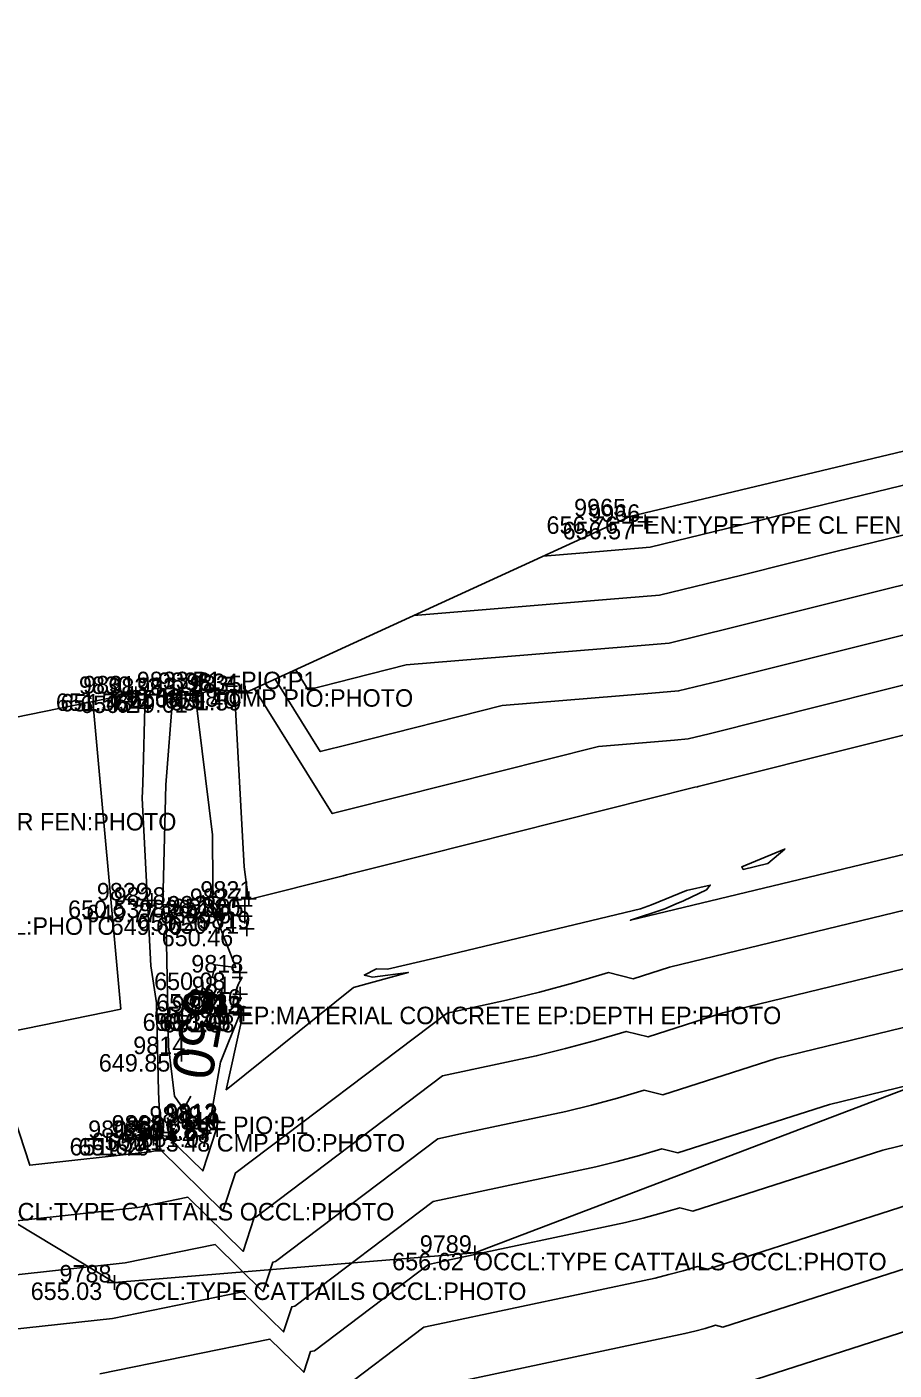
# Model space of a CAD drawing. Extents: x 2129350 to 2137777, y 657588 to 659885.
# Drawn here: x 2133958.2 to 2134017.7, y 659044.8 to 659137 of the extents above; entities that cross this region are included whole.
import ezdxf

# ---------------------------------------------------------------- set-up
doc = ezdxf.new("R2010")
doc.units = 0
for name, color, linetype in [('DT_X_Contour_Major', 7, 'Continuous'), ('DT_X_Contour_Minor', 7, 'Continuous'), ('DT_X_TIN_Hull', 7, 'Continuous'), ('SV_X_Occupation_Line', 7, 'Continuous'), ('SV_X_Shot_Marker', 7, 'Continuous'), ('SV_X_Text_Comment', 7, 'Continuous'), ('SV_X_Text_Description', 7, 'Continuous'), ('SV_X_Text_Elevation', 7, 'Continuous'), ('SV_X_Text_Name', 7, 'Continuous')]:
    doc.layers.add(name, color=color, linetype=linetype)

msp = doc.modelspace()

# ---------------------------------------------------------------- linework, layer by layer
at = {"layer": 'DT_X_Contour_Major'}
for points in [[(2133984.763, 659096.562), (2133998.002, 659097.665), (2134001.64, 659097.968), (2134007.291, 659099.346), (2134013.833, 659100.986), (2134031.695, 659105.339), (2134035.772, 659106.371), (2134054.144, 659110.846), (2134059.912, 659112.305), (2134062.733, 659113.033), (2134082.191, 659118.049), (2134082.236, 659118.06)], [(2133970.96, 659071.806), (2133971.072, 659072.3), (2133971.145, 659072.61), (2133972.548, 659072.42), (2133971.228, 659075.803), (2133971.01, 659076.039), (2133970.955, 659081.1), (2133970.959, 659081.519), (2133969.763, 659091.144)], [(2133968.348, 659091.104), (2133968.238, 659091.09), (2133967.752, 659084.944), (2133967.54, 659076.833), (2133967.77, 659075.29), (2133967.948, 659067.002), (2133968.355, 659063.607), (2133968.956, 659062.7), (2133969.468, 659063.591)], [(2133949.597, 659046.76), (2133964.098, 659048.355), (2133973.018, 659050.173), (2133975.83, 659047.42), (2133976.393, 659049.146), (2133976.617, 659049.192), (2133986.103, 659056.365), (2133987.605, 659056.69), (2133997.253, 659058.741), (2133998.731, 659059.107), (2134000.25, 659059.52), (2134001.796, 659059.974), (2134002.899, 659059.699), (2134013.292, 659063.037), (2134025.401, 659065.979), (2134026.335, 659066.172), (2134030.508, 659067.186), (2134032.419, 659068.346), (2134033.637, 659067.879), (2134042.451, 659069.822)]]:
    msp.add_lwpolyline(points, dxfattribs=at)
at = {"layer": 'DT_X_Contour_Minor'}
for points in [[(2133976.674, 659092.847), (2133977.522, 659091.483), (2133980.569, 659092.251), (2133984.24, 659093.177), (2133999.557, 659094.453), (2134002.293, 659094.681), (2134006.542, 659095.717), (2134017.451, 659098.452), (2134030.921, 659101.735), (2134037.914, 659103.505), (2134051.837, 659106.896), (2134062.046, 659109.479), (2134064.2, 659110.034), (2134079.051, 659113.863), (2134086.408, 659115.608), (2134096.359, 659117.968), (2134110.672, 659121.688), (2134113.284, 659122.316), (2134123.738, 659124.847), (2134133.178, 659127.116), (2134143.637, 659129.649), (2134152.762, 659131.842), (2134168.026, 659135.54)], [(2134167.919, 659131.932), (2134158.207, 659129.579), (2134143.576, 659126.064), (2134136.854, 659124.435), (2134122.145, 659120.901), (2134115.361, 659119.258), (2134111.231, 659118.265), (2134101.918, 659115.845), (2134086.965, 659112.298), (2134075.91, 659109.676), (2134065.666, 659107.035), (2134064.18, 659106.652), (2134049.53, 659102.946), (2134040.056, 659100.638), (2134030.148, 659098.13), (2134021.07, 659095.918), (2134005.794, 659092.088), (2134002.946, 659091.394), (2134001.112, 659091.241), (2133990.847, 659090.386), (2133980.378, 659087.745), (2133978.347, 659087.233), (2133975.261, 659092.198)], [(2133993.65, 659100.644), (2133996.447, 659100.877), (2134000.987, 659101.255), (2134008.04, 659102.975), (2134010.215, 659103.52), (2134032.469, 659108.943), (2134033.63, 659109.237), (2134056.451, 659114.796), (2134057.778, 659115.132), (2134061.267, 659116.032), (2134084.359, 659121.985), (2134084.561, 659122.058), (2134088.214, 659123.011), (2134109.184, 659128.595), (2134118.743, 659130.987)], [(2134163.653, 659127.317), (2134143.515, 659122.478), (2134140.529, 659121.755), (2134120.552, 659116.954), (2134117.438, 659116.2), (2134111.791, 659114.843), (2134107.476, 659113.722), (2134087.522, 659108.989), (2134072.77, 659105.489), (2134067.132, 659104.036), (2134066.314, 659103.825), (2134047.223, 659098.996), (2134042.198, 659097.772), (2134029.374, 659094.526), (2134024.688, 659093.384), (2134005.045, 659088.459), (2134003.599, 659088.107), (2134002.668, 659088.029), (2133997.455, 659087.595), (2133980.186, 659083.24), (2133979.173, 659082.984), (2133973.849, 659091.549)], [(2134095.816, 659107.514), (2134088.079, 659105.679), (2134069.63, 659101.303), (2134068.598, 659101.037), (2134068.448, 659100.998), (2134044.916, 659095.046), (2134044.34, 659094.906), (2134028.6, 659090.922), (2134028.306, 659090.85), (2134004.296, 659084.83), (2134004.251, 659084.82), (2134004.223, 659084.817), (2134004.063, 659084.804), (2133982.451, 659079.354), (2133980.16, 659078.782), (2133979.923, 659078.72), (2133973.446, 659077.098), (2133973.417, 659077.074), (2133973.133, 659079.326), (2133972.456, 659091.406)], [(2133966.328, 659091.154), (2133966.179, 659085.021), (2133966.132, 659084.042), (2133966.732, 659072.529), (2133967.109, 659070), (2133967.24, 659063.89), (2133967.398, 659060.899), (2133967.856, 659060.846), (2133970.284, 659058.468), (2133971.205, 659061.291), (2133971.257, 659061.318), (2133970.798, 659061.748), (2133970.765, 659061.8), (2133971.506, 659065.941), (2133972.802, 659069.177), (2133972.807, 659069.197), (2133972.801, 659069.373), (2133972.939, 659069.216), (2133972.939, 659069.194), (2133972.952, 659068.84), (2133972.952, 659068.822), (2133972.921, 659068.684), (2133971.901, 659064.036), (2133980.635, 659071.043), (2133984.389, 659072.088), (2133981.931, 659071.766), (2133981.659, 659071.831), (2133981.367, 659071.901), (2133982.216, 659072.326), (2133982.975, 659072.314), (2133986.215, 659073.069), (2134000.328, 659076.44), (2134001.091, 659076.732), (2134003.49, 659077.7), (2134005.113, 659078.081), (2134004.854, 659077.758), (2134003.279, 659077.002), (2134002.787, 659076.786), (2134001.995, 659076.438), (2133999.642, 659075.668), (2134018.561, 659080.227)], [(2133962.734, 659090.671), (2133964.656, 659069.566), (2133945.043, 659065.553)], [(2133985.855, 659043.583), (2134003.377, 659047.309), (2134004.058, 659047.477), (2134004.757, 659047.668), (2134005.469, 659047.877), (2134005.976, 659047.75), (2134024.269, 659053.625), (2134028.407, 659054.63), (2134030.054, 659054.97), (2134031.451, 659055.309), (2134034.821, 659057.356), (2134036.97, 659056.532), (2134041.073, 659057.437), (2134056.258, 659058.478), (2134069.282, 659066.027), (2134077.71, 659067.617), (2134077.927, 659067.658), (2134087.349, 659069.428), (2134121.013, 659079.703), (2134124.053, 659080.211), (2134127.308, 659081.14), (2134164.102, 659088.042)], [(2133963.234, 659044.551), (2133974.897, 659046.928), (2133977.216, 659044.658), (2133977.681, 659046.081), (2133977.961, 659046.138), (2133985.783, 659052.053), (2133987.022, 659052.321), (2133999.295, 659054.931), (2134000.507, 659055.23), (2134001.752, 659055.57), (2134003.02, 659055.942), (2134003.924, 659055.716), (2134016.951, 659059.9), (2134026.403, 659062.196), (2134027.575, 659062.438), (2134030.823, 659063.227), (2134033.22, 659064.682), (2134034.748, 659064.097), (2134044.461, 659066.238), (2134055.463, 659066.993), (2134072.632, 659076.944), (2134074.956, 659077.482), (2134078.271, 659078.486), (2134116.21, 659087.131)], [(2133979.305, 659043.085), (2133985.463, 659047.741), (2133986.439, 659047.952), (2134001.336, 659051.12), (2134002.282, 659051.354), (2134003.255, 659051.619), (2134004.244, 659051.909), (2134004.95, 659051.733), (2134020.61, 659056.762), (2134027.405, 659058.413), (2134028.814, 659058.704), (2134031.137, 659059.268), (2134034.021, 659061.019), (2134035.859, 659060.314), (2134042.767, 659061.837), (2134055.861, 659062.736), (2134074.558, 659073.572), (2134075.929, 659073.831), (2134075.965, 659073.838), (2134077.498, 659074.126), (2134086.096, 659076.75), (2134120.442, 659084.577)], [(2134007.002, 659043.767), (2134027.928, 659050.488), (2134029.41, 659050.848), (2134031.294, 659051.236), (2134031.765, 659051.351), (2134035.622, 659053.692), (2134038.081, 659052.75), (2134039.378, 659053.036), (2134056.656, 659054.221), (2134064.007, 659058.482), (2134079.49, 659061.402), (2134079.89, 659061.478), (2134097.201, 659064.73), (2134113.485, 659069.7), (2134126.289, 659071.838), (2134139.998, 659075.753), (2134158.234, 659079.174), (2134175.353, 659083.764)], [(2134010.206, 659080.536), (2134010.237, 659080.549), (2134010.225, 659080.538), (2134009.064, 659079.551), (2134007.382, 659079.153), (2134007.272, 659079.32), (2134010.206, 659080.536)], [(2133957.38, 659062.078), (2133958.413, 659058.858), (2133966.69, 659059.769), (2133967.378, 659059.909), (2133971.67, 659055.706), (2133972.53, 659058.341), (2133972.585, 659058.352), (2133987.063, 659069.3), (2133989.356, 659069.797), (2133991.13, 659070.174), (2133993.405, 659070.736), (2133995.743, 659071.373), (2133998.123, 659072.072), (2133999.821, 659071.649), (2134002.314, 659072.449), (2134022.394, 659077.328)], [(2133943.581, 659053.517), (2133965.826, 659055.964), (2133969.258, 659056.664), (2133973.057, 659052.944), (2133973.818, 659055.276), (2133973.929, 659055.299), (2133986.743, 659064.988), (2133988.772, 659065.428), (2133993.171, 659066.363), (2133995.181, 659066.859), (2133997.246, 659067.422), (2133999.347, 659068.039), (2134000.847, 659067.665), (2134005.973, 659069.312), (2134023.397, 659073.545)], [(2133945.621, 659050.032), (2133964.962, 659052.16), (2133971.138, 659053.419), (2133974.443, 659050.182), (2133975.105, 659052.211), (2133975.273, 659052.245), (2133986.423, 659060.677), (2133988.189, 659061.059), (2133995.212, 659062.552), (2133996.956, 659062.983), (2133998.748, 659063.471), (2134000.571, 659064.007), (2134001.873, 659063.682), (2134009.632, 659066.175), (2134024.399, 659069.762)]]:
    msp.add_lwpolyline(points, dxfattribs=at)
at = {"layer": 'DT_X_TIN_Hull'}
msp.add_lwpolyline([(2134356.026, 659185.946), (2134303.515, 659173.01), (2134259.229, 659162.306), (2134216.068, 659153.312), (2134168.251, 659141.961), (2134125.876, 659132.549), (2134109.045, 659128.864), (2134056.892, 659117.026), (2133999.593, 659103.374), (2133973.207, 659091.255), (2133972.954, 659091.387), (2133971.1, 659091.461), (2133969.763, 659091.144), (2133967.604, 659091.082), (2133965.702, 659091.19), (2133965.451, 659091.228), (2133933.981, 659084.789), (2133923.278, 659083.026), (2133873.948, 659069.271), (2133819.308, 659054.807), (2133767.477, 659040.462), (2133725.976, 659030.566)], dxfattribs=at)
at = {"layer": 'SV_X_Occupation_Line'}
msp.add_line((2133964.235, 659050.817), (2133955.172, 659056.273), dxfattribs=at)
msp.add_lwpolyline([(2133964.235, 659050.817), (2133988.958, 659052.851), (2134023.903, 659066.142), (2134068.855, 659084.352), (2134158.11, 659108.791), (2134245.538, 659131.154), (2134308.77, 659149.808)], dxfattribs=at)
at = {"layer": 'SV_X_Shot_Marker'}
for p, q in [((2133999.095, 659103.374), (2134000.095, 659103.374)), ((2133999.595, 659103.874), (2133999.595, 659102.874)), ((2133999.595, 659103.374), (2133999.595, 659103.374)), ((2134000.643, 659103.497), (2134000.643, 659102.497)), ((2134000.143, 659102.997), (2134001.143, 659102.997)), ((2134000.643, 659102.997), (2134000.643, 659102.997)), ((2133964.953, 659091.228), (2133965.953, 659091.228)), ((2133965.204, 659091.19), (2133966.204, 659091.19)), ((2133965.453, 659091.728), (2133965.453, 659090.728)), ((2133965.453, 659091.228), (2133965.453, 659091.228)), ((2133965.704, 659091.69), (2133965.704, 659090.69)), ((2133965.704, 659091.19), (2133965.704, 659091.19)), ((2133967.606, 659091.583), (2133967.606, 659090.583)), ((2133969.597, 659091.605), (2133969.597, 659090.605)), ((2133970.602, 659091.461), (2133971.602, 659091.461)), ((2133971.102, 659091.961), (2133971.102, 659090.961)), ((2133971.102, 659091.461), (2133971.102, 659091.461)), ((2133972.456, 659091.387), (2133973.456, 659091.387)), ((2133972.709, 659091.255), (2133973.709, 659091.255)), ((2133972.956, 659091.887), (2133972.956, 659090.887)), ((2133972.956, 659091.387), (2133972.956, 659091.387)), ((2133973.209, 659091.755), (2133973.209, 659090.755)), ((2133973.209, 659091.255), (2133973.209, 659091.255)), ((2133967.106, 659091.083), (2133968.106, 659091.083)), ((2133967.606, 659091.083), (2133967.606, 659091.083)), ((2133969.097, 659091.105), (2133970.097, 659091.105)), ((2133969.597, 659091.105), (2133969.597, 659091.105)), ((2133966.798, 659077.524), (2133966.798, 659076.524)), ((2133973.458, 659077.644), (2133973.458, 659076.644)), ((2133966.298, 659077.024), (2133967.298, 659077.024)), ((2133966.798, 659077.024), (2133966.798, 659077.024)), ((2133967.451, 659076.729), (2133968.451, 659076.729)), ((2133967.951, 659077.229), (2133967.951, 659076.229)), ((2133967.951, 659076.729), (2133967.951, 659076.729)), ((2133971.632, 659076.628), (2133971.632, 659075.628)), ((2133972.674, 659076.645), (2133973.674, 659076.645)), ((2133972.958, 659077.144), (2133973.958, 659077.144)), ((2133973.174, 659077.145), (2133973.174, 659076.145)), ((2133973.174, 659076.645), (2133973.174, 659076.645)), ((2133973.181, 659076.437), (2133973.181, 659075.437)), ((2133973.458, 659077.144), (2133973.458, 659077.144)), ((2133969.26, 659075.86), (2133970.26, 659075.86)), ((2133969.76, 659076.36), (2133969.76, 659075.36)), ((2133969.76, 659075.86), (2133969.76, 659075.86)), ((2133971.132, 659076.128), (2133972.132, 659076.128)), ((2133971.632, 659076.128), (2133971.632, 659076.128)), ((2133972.681, 659075.937), (2133973.681, 659075.937)), ((2133973.181, 659075.937), (2133973.181, 659075.937)), ((2133973.309, 659075.583), (2133973.309, 659074.583)), ((2133972.809, 659075.083), (2133973.809, 659075.083)), ((2133973.309, 659075.083), (2133973.309, 659075.083)), ((2133972.326, 659072.08), (2133973.326, 659072.08)), ((2133972.826, 659072.58), (2133972.826, 659071.58)), ((2133972.826, 659072.08), (2133972.826, 659072.08)), ((2133972.852, 659071.106), (2133972.852, 659070.106)), ((2133972.352, 659070.606), (2133973.352, 659070.606)), ((2133972.72, 659070.235), (2133972.72, 659069.235)), ((2133972.852, 659070.606), (2133972.852, 659070.606)), ((2133971.424, 659069.276), (2133972.424, 659069.276)), ((2133971.924, 659069.776), (2133971.924, 659068.776)), ((2133971.924, 659069.276), (2133971.924, 659069.276)), ((2133972.22, 659069.735), (2133973.22, 659069.735)), ((2133972.349, 659069.172), (2133973.349, 659069.172)), ((2133972.574, 659069.251), (2133973.574, 659069.251)), ((2133972.577, 659069.283), (2133973.577, 659069.283)), ((2133972.72, 659069.735), (2133972.72, 659069.735)), ((2133972.849, 659069.672), (2133972.849, 659068.672)), ((2133972.849, 659069.172), (2133972.849, 659069.172)), ((2133973.074, 659069.751), (2133973.074, 659068.751)), ((2133973.074, 659069.251), (2133973.074, 659069.251)), ((2133973.077, 659069.783), (2133973.077, 659068.783)), ((2133973.077, 659069.283), (2133973.077, 659069.283)), ((2133968.325, 659066.482), (2133969.325, 659066.482)), ((2133968.825, 659066.982), (2133968.825, 659065.982)), ((2133968.825, 659066.482), (2133968.825, 659066.482)), ((2133970.04, 659061.715), (2133971.04, 659061.715)), ((2133970.502, 659061.888), (2133971.502, 659061.888)), ((2133970.54, 659062.215), (2133970.54, 659061.215)), ((2133970.54, 659061.715), (2133970.54, 659061.715)), ((2133970.56, 659061.783), (2133971.56, 659061.783)), ((2133971.002, 659062.388), (2133971.002, 659061.388)), ((2133971.002, 659061.888), (2133971.002, 659061.888)), ((2133971.06, 659062.283), (2133971.06, 659061.283)), ((2133971.06, 659061.783), (2133971.06, 659061.783)), ((2133971.288, 659061.802), (2133971.288, 659060.802)), ((2133965.826, 659060.731), (2133966.826, 659060.731)), ((2133966.326, 659061.231), (2133966.326, 659060.231)), ((2133966.326, 659060.731), (2133966.326, 659060.731)), ((2133966.408, 659060.724), (2133967.408, 659060.724)), ((2133966.908, 659061.224), (2133966.908, 659060.224)), ((2133966.908, 659060.724), (2133966.908, 659060.724)), ((2133967.448, 659061.095), (2133968.448, 659061.095)), ((2133967.948, 659061.595), (2133967.948, 659060.595)), ((2133967.948, 659061.095), (2133967.948, 659061.095)), ((2133970.788, 659061.302), (2133971.788, 659061.302)), ((2133971.288, 659061.302), (2133971.288, 659061.302)), ((2133988.958, 659053.351), (2133988.958, 659052.351)), ((2133988.458, 659052.851), (2133989.458, 659052.851)), ((2133988.958, 659052.851), (2133988.958, 659052.851)), ((2133963.735, 659050.817), (2133964.735, 659050.817)), ((2133964.235, 659051.317), (2133964.235, 659050.317)), ((2133964.235, 659050.817), (2133964.235, 659050.817))]:
    msp.add_line(p, q, dxfattribs=at)

# ---------------------------------------------------------------- texts
at = {"layer": 'DT_X_Contour_Major'}
msp.add_text('650', height=2.8, rotation=259.70572, dxfattribs=at).set_placement((2133969.243, 659071.236))
at = {"layer": 'SV_X_Text_Comment'}
for s, p in [('FEN:TYPE TYPE CL FEN:HEIGHT FEN:OWNER FEN:PHOTO', (2133999.595, 659102.174)), ('48 CMP PIO:PHOTO', (2133969.572, 659090.315)), ('FEN:TYPE TYPE CL FEN:HEIGHT FEN:OWNER FEN:PHOTO', (2133923.28, 659081.826)), ('OCCL:TYPE CATTAILS OCCL:PHOTO', (2133936.042, 659074.665)), ('EP:MATERIAL CONCRETE EP:DEPTH EP:PHOTO', (2133972.72, 659068.535)), ('48 CMP PIO:PHOTO', (2133969.017, 659059.796)), ('OCCL:TYPE CATTAILS OCCL:PHOTO', (2133955.172, 659055.073)), ('OCCL:TYPE CATTAILS OCCL:PHOTO', (2133988.958, 659051.651)), ('OCCL:TYPE CATTAILS OCCL:PHOTO', (2133964.235, 659049.617))]:
    msp.add_text(s, height=1.2, dxfattribs=at).set_placement(p)
at = {"layer": 'SV_X_Text_Description'}
for p in [(2133969.572, 659091.515), (2133969.017, 659060.996)]:
    msp.add_text('P1= PIO:P1', height=1.2, dxfattribs=at).set_placement(p)
at = {"layer": 'SV_X_Text_Elevation'}
for s, p in [('656.76', (2133993.879, 659102.174)), ('656.57', (2133994.984, 659101.797)), ('651.56', (2133960.21, 659090.028)), ('651.43', (2133960.527, 659089.99)), ('649.58', (2133963.894, 659090.315)), ('650.05', (2133965.235, 659090.261)), ('651.40', (2133967.675, 659090.187)), ('651.59', (2133968.032, 659090.055)), ('650.24', (2133961.88, 659089.883)), ('649.61', (2133964.343, 659089.905)), ('650.53', (2133961.044, 659075.824)), ('649.77', (2133962.301, 659075.529)), ('650.96', (2133967.326, 659075.445)), ('651.05', (2133968.177, 659075.944)), ('649.60', (2133963.968, 659074.66)), ('650.26', (2133965.821, 659074.928)), ('650.71', (2133967.88, 659074.737)), ('650.46', (2133967.47, 659073.883)), ('650.08', (2133966.949, 659070.88)), ('650.43', (2133967.089, 659069.406)), ('650.34', (2133966.161, 659068.076)), ('650.98', (2133966.938, 659068.535)), ('650.98', (2133967.292, 659068.051)), ('650.99', (2133967.295, 659068.083)), ('651.08', (2133967.559, 659067.972)), ('649.85', (2133963.156, 659065.282)), ('650.22', (2133964.814, 659060.515)), ('651.89', (2133965.825, 659060.688)), ('651.87', (2133965.892, 659060.583)), ('651.62', (2133961.149, 659059.531)), ('651.79', (2133961.75, 659059.524)), ('650.21', (2133962.647, 659059.895)), ('650.13', (2133963.736, 659059.796)), ('651.07', (2133966.007, 659060.102)), ('656.62', (2133983.289, 659051.651)), ('655.03', (2133958.481, 659049.617))]:
    msp.add_text(s, height=1.2, dxfattribs=at).set_placement(p)
at = {"layer": 'SV_X_Text_Name'}
for s, p in [('9965', (2133995.769, 659103.374)), ('9966', (2133996.741, 659102.997)), ('9830', (2133961.792, 659091.19)), ('9831', (2133962.079, 659091.228)), ('9832', (2133963.808, 659091.083)), ('9833', (2133965.764, 659091.515)), ('9837', (2133965.789, 659091.105)), ('9836', (2133967.219, 659091.461)), ('9834', (2133969.158, 659091.387)), ('9835', (2133969.401, 659091.255)), ('9829', (2133963.019, 659077.024)), ('9821', (2133970.122, 659077.144)), ('9828', (2133964.172, 659076.729)), ('9825', (2133967.862, 659076.128)), ('9827', (2133969.404, 659076.645)), ('9826', (2133965.915, 659075.86)), ('9820', (2133969.307, 659075.937)), ('9819', (2133969.984, 659075.083)), ('9818', (2133969.501, 659072.08)), ('9817', (2133969.536, 659070.606)), ('9816', (2133969.329, 659069.735)), ('9824', (2133968.164, 659069.276)), ('9823', (2133969.304, 659069.251)), ('9822', (2133969.317, 659069.283)), ('9815', (2133969.533, 659069.172)), ('9814', (2133965.519, 659066.482)), ('9809', (2133966.628, 659061.715)), ('9812', (2133967.696, 659061.888)), ('9813', (2133967.744, 659061.783)), ('9807', (2133962.424, 659060.731)), ('9811', (2133964.026, 659060.724)), ('9808', (2133964.036, 659061.095)), ('9806', (2133965.039, 659060.996)), ('9810', (2133967.868, 659061.302)), ('9789', (2133985.179, 659052.851)), ('9788', (2133960.456, 659050.817))]:
    msp.add_text(s, height=1.2, dxfattribs=at).set_placement(p)

doc.saveas('drawing.dxf')
